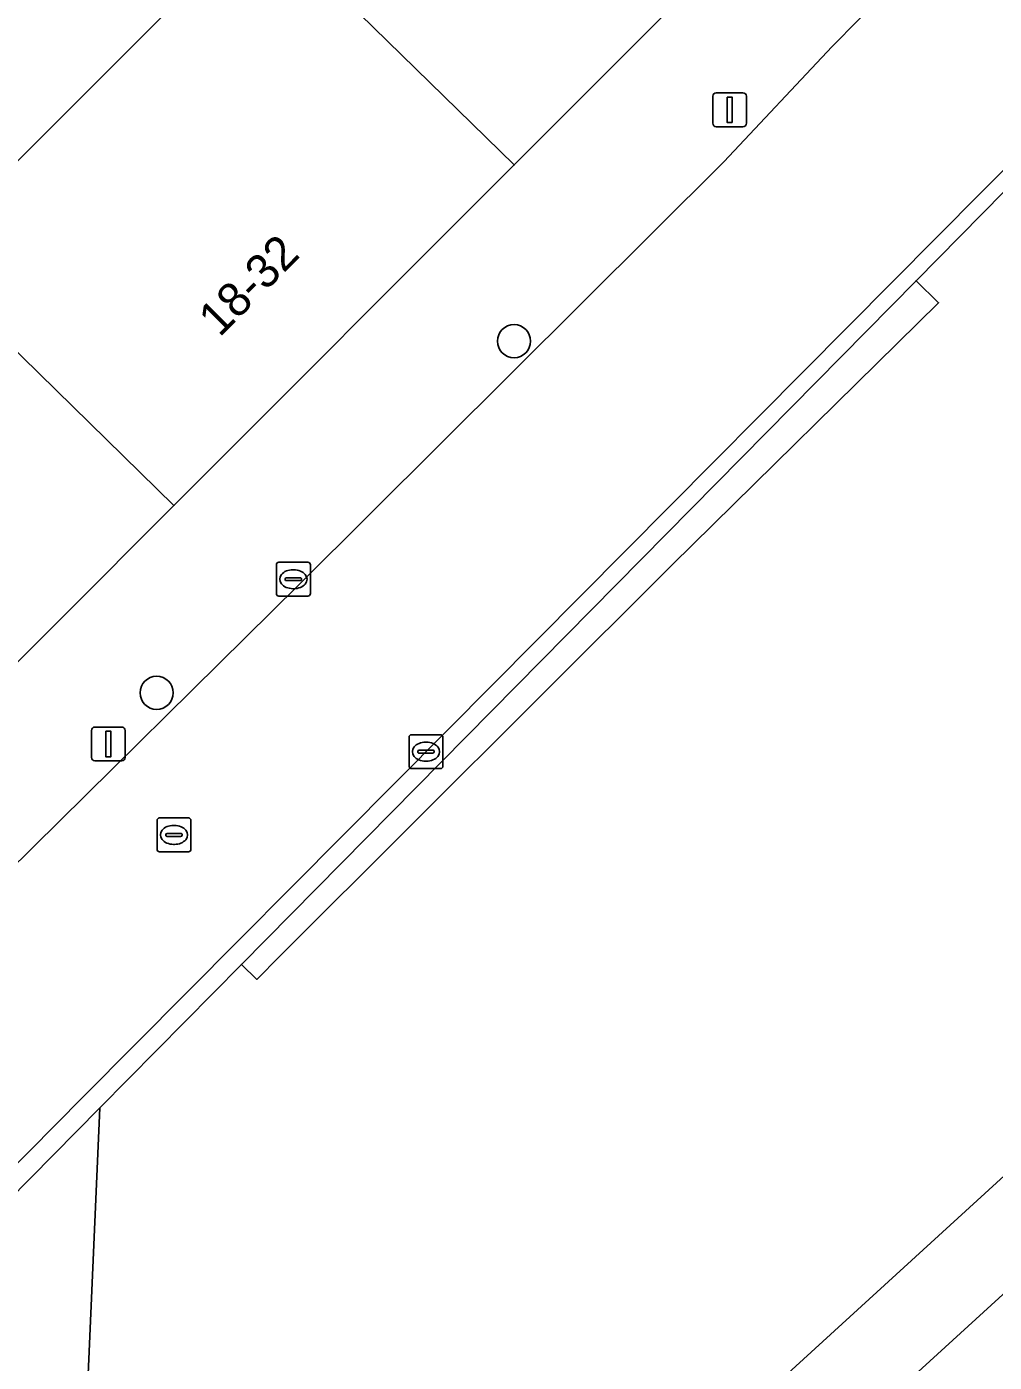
# Model space of a CAD drawing. Extents: x 159888 to 160761, y 384031 to 384750.
# Drawn here: x 160388.95 to 160417.48, y 384258.44 to 384297.83 of the extents above; entities that cross this region are included whole.
import ezdxf

# ---------------------------------------------------------------- set-up
doc = ezdxf.new("R2010")
doc.units = 0
for name, color, linetype in [('IMGEO_Boom', 7, 'Continuous'), ('IMGEO_Erf', 7, 'Continuous'), ('IMGEO_Groenvoorziening', 7, 'Continuous'), ('IMGEO_Kolk', 7, 'Continuous'), ('IMGEO_Lichtmast', 7, 'Continuous'), ('IMGEO_Pand', 7, 'Continuous'), ('IMGEO_Pand_nummerreeks', 7, 'Continuous'), ('IMGEO_Rijbaan_lokaal_open', 7, 'Continuous'), ('IMGEO_Rioolput', 7, 'Continuous'), ('IMGEO_Voetpad_halfverhard', 7, 'Continuous'), ('IMGEO_Voetpad_open', 7, 'Continuous')]:
    doc.layers.add(name, color=color, linetype=linetype)

msp = doc.modelspace()

# ---------------------------------------------------------------- linework, layer by layer
at = {"layer": 'IMGEO_Boom'}
for centre in [(160403.319, 384288.557), (160392.78, 384278.186)]:
    msp.add_circle(centre, 0.489, dxfattribs=at)
at = {"layer": 'IMGEO_Erf'}
for points in [[(160407.134, 384312.362), (160404.095, 384316.885), (160401.57, 384314.532), (160372.039, 384285.135), (160362.772, 384285.007), (160362.837, 384279.095), (160351.699, 384267.85), (160345.439, 384274.748), (160345.355, 384284.72), (160341.199, 384284.583), (160337.275, 384280.219), (160336.483, 384279.562), (160360.504, 384250.764), (160363.191, 384253.558), (160355.746, 384260.844), (160365.773, 384270.9), (160375.799, 384280.956), (160385.826, 384291.012), (160395.852, 384301.068), (160405.753, 384310.998)], [(160415.894, 384247.195), (160418.994, 384250), (160426.423, 384256.722), (160436.74, 384266.058), (160437.684, 384267.073), (160432.866, 384274.257), (160406.309, 384250), (160394.332, 384239.06), (160393.278, 384238.132), (160385.071, 384230.903), (160377.553, 384231.423), (160373.824, 384235.664), (160374.226, 384244.326), (160369.777, 384244.623), (160364.144, 384239.222), (160389.244, 384208.933), (160391.374, 384210.83), (160384.306, 384218.612), (160394.835, 384228.14), (160405.365, 384237.667)]]:
    msp.add_lwpolyline(points, close=True, dxfattribs=at)
at = {"layer": 'IMGEO_Groenvoorziening'}
msp.add_lwpolyline([(160418.424, 384293.635), (160415.176, 384290.342), (160415.838, 384289.689), (160407.979, 384281.961), (160396.416, 384270.415), (160395.73, 384269.729), (160395.281, 384270.172), (160391.104, 384265.938), (160390.406, 384250), (160390.241, 384246.234), (160394.04, 384242.242), (160402.528, 384250), (160431.422, 384276.411)], dxfattribs=at)
at = {"layer": 'IMGEO_Kolk'}
for p, q in [((160396.312, 384281.11), (160396.312, 384281.962)), ((160396.387, 384282.036), (160397.239, 384282.036)), ((160397.313, 384281.962), (160397.313, 384281.11)), ((160396.571, 384281.53), (160396.571, 384281.542)), ((160396.614, 384281.579), (160397.012, 384281.579)), ((160396.8, 384281.816), (160396.825, 384281.816)), ((160397.055, 384281.542), (160397.055, 384281.53)), ((160397.009, 384281.493), (160396.611, 384281.493)), ((160396.823, 384281.256), (160396.798, 384281.256)), ((160397.239, 384281.036), (160396.387, 384281.036)), ((160400.222, 384276.022), (160400.222, 384276.874)), ((160400.297, 384276.948), (160401.149, 384276.948)), ((160401.223, 384276.874), (160401.223, 384276.022)), ((160400.481, 384276.442), (160400.481, 384276.454)), ((160400.919, 384276.405), (160400.521, 384276.405)), ((160400.524, 384276.491), (160400.922, 384276.491)), ((160400.71, 384276.728), (160400.735, 384276.728)), ((160400.965, 384276.454), (160400.965, 384276.442)), ((160400.733, 384276.168), (160400.708, 384276.168)), ((160401.149, 384275.948), (160400.297, 384275.948))]:
    msp.add_line(p, q, dxfattribs=at)
for points in [[(160396.312, 384281.11), (160396.312, 384281.962)], [(160396.387, 384282.036), (160397.239, 384282.036)], [(160397.313, 384281.962), (160397.313, 384281.11)], [(160397.239, 384281.036), (160396.387, 384281.036)], [(160400.222, 384276.022), (160400.222, 384276.874)], [(160400.297, 384276.948), (160401.149, 384276.948)], [(160401.223, 384276.874), (160401.223, 384276.022)], [(160401.149, 384275.948), (160400.297, 384275.948)]]:
    msp.add_lwpolyline(points, dxfattribs=at)
for centre, radius, start, end in [((160396.389, 384281.96), 0.0765, 91.552, 178.448), ((160396.389, 384281.96), 0.0765, 91.552, 178.448), ((160397.237, 384281.96), 0.0765, 1.552, 88.448), ((160397.237, 384281.96), 0.0765, 1.552, 88.448), ((160396.611, 384281.539), 0.0403, 85.8775, 175.7526), ((160396.608, 384281.529), 0.0366, 178.938, 274.7102), ((160397.012, 384281.536), 0.043, 264.8664, 352.4533), ((160397.016, 384281.541), 0.0386, 1.7309, 96.639), ((160396.389, 384281.112), 0.0765, 181.552, 268.448), ((160396.389, 384281.112), 0.0765, 181.552, 268.448), ((160397.237, 384281.112), 0.0765, 271.552, 358.448), ((160397.237, 384281.112), 0.0765, 271.552, 358.448), ((160400.299, 384276.872), 0.0765, 91.552, 178.448), ((160400.299, 384276.872), 0.0765, 91.552, 178.448), ((160401.147, 384276.872), 0.0765, 1.552, 88.448), ((160401.147, 384276.872), 0.0765, 1.552, 88.448), ((160400.521, 384276.451), 0.0403, 85.8775, 175.7526), ((160400.518, 384276.441), 0.0366, 178.938, 274.7102), ((160400.922, 384276.448), 0.043, 264.8664, 352.4533), ((160400.926, 384276.453), 0.0386, 1.7309, 96.639), ((160400.299, 384276.024), 0.0765, 181.552, 268.448), ((160400.299, 384276.024), 0.0765, 181.552, 268.448), ((160401.147, 384276.024), 0.0765, 271.552, 358.448), ((160401.147, 384276.024), 0.0765, 271.552, 358.448)]:
    msp.add_arc(centre, radius, start, end, dxfattribs=at)
for centre, major_axis, ratio, start_param, end_param in [((160396.799, 384281.536), (-0.387, 0.002), 0.722429, 4.712389, 7.853982), ((160396.824, 384281.536), (-0.39, 0.002), 0.717154, 1.570796, 4.712389), ((160400.709, 384276.448), (-0.387, 0.002), 0.722429, 4.712389, 7.853982), ((160400.734, 384276.448), (-0.39, 0.002), 0.717154, 1.570796, 4.712389)]:
    msp.add_ellipse(centre, major_axis=major_axis, ratio=ratio, start_param=start_param, end_param=end_param, dxfattribs=at)
at = {"layer": 'IMGEO_Lichtmast'}
for p, q in [((160409.179, 384294.985), (160409.179, 384295.785)), ((160409.179, 384295.785), (160409.179, 384294.985)), ((160409.279, 384295.885), (160410.069, 384295.885)), ((160410.069, 384295.885), (160409.279, 384295.885)), ((160410.169, 384295.785), (160410.169, 384294.985)), ((160410.169, 384294.985), (160410.169, 384295.785)), ((160410.069, 384294.885), (160409.279, 384294.885)), ((160409.279, 384294.885), (160410.069, 384294.885)), ((160390.96, 384277.175), (160391.75, 384277.175)), ((160391.75, 384277.175), (160390.96, 384277.175)), ((160390.86, 384276.275), (160390.86, 384277.075)), ((160390.86, 384277.075), (160390.86, 384276.275)), ((160391.85, 384277.075), (160391.85, 384276.275)), ((160391.85, 384276.275), (160391.85, 384277.075)), ((160391.75, 384276.175), (160390.96, 384276.175)), ((160390.96, 384276.175), (160391.75, 384276.175))]:
    msp.add_line(p, q, dxfattribs=at)
for points in [[(160409.599, 384295.76), (160409.749, 384295.76), (160409.749, 384295.01), (160409.599, 384295.01), (160409.599, 384295.76)], [(160391.28, 384277.05), (160391.43, 384277.05), (160391.43, 384276.3), (160391.28, 384276.3), (160391.28, 384277.05)]]:
    msp.add_lwpolyline(points, dxfattribs=at)
for centre, start, end in [((160409.279, 384295.785), 90, 180), ((160409.279, 384295.785), 90, 180), ((160410.069, 384295.785), 0, 90), ((160410.069, 384295.785), 360, 90), ((160409.279, 384294.985), 180, 270), ((160409.279, 384294.985), 180, 270), ((160410.069, 384294.985), 270, 0), ((160410.069, 384294.985), 270, 0), ((160390.96, 384277.075), 90, 180), ((160390.96, 384277.075), 90, 180), ((160391.75, 384277.075), 0, 90), ((160391.75, 384277.075), 360, 90), ((160390.96, 384276.275), 180, 270), ((160390.96, 384276.275), 180, 270), ((160391.75, 384276.275), 270, 0), ((160391.75, 384276.275), 270, 0)]:
    msp.add_arc(centre, 0.1, start, end, dxfattribs=at)
at = {"layer": 'IMGEO_Pand'}
for points in [[(160395.852, 384301.068), (160403.325, 384293.755), (160413.221, 384303.667), (160405.753, 384310.998)], [(160393.291, 384283.706), (160403.325, 384293.755), (160395.852, 384301.068), (160385.826, 384291.012)], [(160383.258, 384273.657), (160393.291, 384283.706), (160385.826, 384291.012), (160375.799, 384280.956)]]:
    msp.add_lwpolyline(points, close=True, dxfattribs=at)
at = {"layer": 'IMGEO_Rijbaan_lokaal_open'}
for points in [[(160422.932, 384294.34), (160417.91, 384301.776), (160415.801, 384300.405), (160412.696, 384297.247), (160409.504, 384293.847), (160396.973, 384281.372), (160379.726, 384264.338), (160372.559, 384257.094), (160366.063, 384250.659), (160365.342, 384250), (160363.109, 384247.959), (160360.237, 384245.231), (160359.808, 384244.824), (160358.837, 384243.977), (160356.862, 384242.381), (160355.12, 384241.215), (160350.961, 384238.084), (160345.716, 384234.364), (160345.542, 384234.231)], [(160344.158, 384231.267), (160343.475, 384230.828), (160346.326, 384226.816), (160346.553, 384226.989), (160354.699, 384232.863), (160360.784, 384237.351), (160361.189, 384237.649), (160363.689, 384239.781), (160364.647, 384240.62), (160366.673, 384242.576), (160373.037, 384248.641), (160374.399, 384250), (160384.224, 384259.805), (160390.609, 384266.27), (160401.354, 384277.085), (160418.41, 384294.276)]]:
    msp.add_lwpolyline(points, dxfattribs=at)
at = {"layer": 'IMGEO_Rioolput'}
for p, q in [((160392.791, 384273.567), (160392.791, 384274.419)), ((160392.866, 384274.493), (160393.718, 384274.493)), ((160393.792, 384274.419), (160393.792, 384273.567)), ((160393.093, 384274.036), (160393.491, 384274.036)), ((160393.279, 384274.273), (160393.304, 384274.273)), ((160393.05, 384273.987), (160393.05, 384273.999)), ((160393.488, 384273.95), (160393.09, 384273.95)), ((160393.302, 384273.713), (160393.277, 384273.713)), ((160393.534, 384273.999), (160393.534, 384273.987)), ((160393.718, 384273.493), (160392.866, 384273.493))]:
    msp.add_line(p, q, dxfattribs=at)
for points in [[(160392.791, 384273.567), (160392.791, 384274.419)], [(160392.866, 384274.493), (160393.718, 384274.493)], [(160393.792, 384274.419), (160393.792, 384273.567)], [(160393.718, 384273.493), (160392.866, 384273.493)]]:
    msp.add_lwpolyline(points, dxfattribs=at)
for centre, radius, start, end in [((160392.868, 384274.417), 0.0765, 91.552, 178.448), ((160392.868, 384274.417), 0.0765, 91.552, 178.448), ((160393.716, 384274.417), 0.0765, 1.552, 88.448), ((160393.716, 384274.417), 0.0765, 1.552, 88.448), ((160393.09, 384273.996), 0.0403, 85.8775, 175.7526), ((160393.495, 384273.998), 0.0386, 1.7309, 96.639), ((160393.087, 384273.986), 0.0366, 178.938, 274.7102), ((160393.491, 384273.993), 0.043, 264.8664, 352.4533), ((160392.868, 384273.569), 0.0765, 181.552, 268.448), ((160392.868, 384273.569), 0.0765, 181.552, 268.448), ((160393.716, 384273.569), 0.0765, 271.552, 358.448), ((160393.716, 384273.569), 0.0765, 271.552, 358.448)]:
    msp.add_arc(centre, radius, start, end, dxfattribs=at)
for centre, major_axis, ratio, start_param, end_param in [((160393.278, 384273.993), (-0.387, 0.002), 0.722429, 4.712389, 7.853982), ((160393.303, 384273.993), (-0.39, 0.002), 0.717154, 1.570796, 4.712389)]:
    msp.add_ellipse(centre, major_axis=major_axis, ratio=ratio, start_param=start_param, end_param=end_param, dxfattribs=at)
at = {"layer": 'IMGEO_Voetpad_halfverhard'}
msp.add_lwpolyline([(160390.241, 384246.234), (160390.406, 384250), (160391.104, 384265.938), (160388.378, 384263.174), (160387.768, 384250), (160387.57, 384245.716), (160371.882, 384246.688), (160369.777, 384244.623), (160374.226, 384244.326), (160388.452, 384243.469), (160393.278, 384238.132), (160394.332, 384239.06), (160406.309, 384250), (160432.866, 384274.257), (160431.422, 384276.411), (160402.528, 384250), (160394.04, 384242.242)], close=True, dxfattribs=at)
at = {"layer": 'IMGEO_Voetpad_open'}
for points in [[(160412.696, 384297.247), (160415.801, 384300.405), (160413.221, 384303.667), (160403.325, 384293.755), (160393.291, 384283.706), (160383.258, 384273.657), (160373.224, 384263.607), (160363.191, 384253.558), (160360.504, 384250.764), (160358.209, 384248.5), (160357.767, 384248.02), (160354.731, 384245.687), (160340.225, 384235.253), (160343.475, 384230.828), (160344.158, 384231.267)], [(160345.542, 384234.231), (160345.716, 384234.364), (160350.961, 384238.084), (160355.12, 384241.215), (160356.862, 384242.381), (160358.837, 384243.977), (160359.808, 384244.824), (160360.237, 384245.231), (160359.618, 384245.884), (160362.49, 384248.612), (160363.109, 384247.959), (160365.342, 384250), (160366.063, 384250.659), (160372.559, 384257.094), (160379.726, 384264.338), (160396.973, 384281.372), (160409.504, 384293.847), (160412.696, 384297.247)], [(160418.41, 384294.276), (160401.354, 384277.085), (160390.609, 384266.27), (160384.224, 384259.805), (160374.399, 384250), (160373.037, 384248.641), (160366.673, 384242.576), (160364.647, 384240.62), (160363.689, 384239.781), (160361.189, 384237.649), (160360.784, 384237.351), (160354.699, 384232.863), (160346.553, 384226.989), (160346.326, 384226.816), (160346.64, 384226.054), (160361.616, 384237.146), (160364.144, 384239.222), (160369.777, 384244.623), (160371.882, 384246.688), (160375.258, 384250), (160388.378, 384263.174), (160391.104, 384265.938), (160395.281, 384270.172), (160415.176, 384290.342)], [(160415.176, 384290.342), (160418.424, 384293.635)]]:
    msp.add_lwpolyline(points, dxfattribs=at)
msp.add_lwpolyline([(160407.979, 384281.961), (160415.838, 384289.689), (160415.176, 384290.342), (160395.281, 384270.172), (160395.73, 384269.729), (160396.416, 384270.415)], close=True, dxfattribs=at)

# ---------------------------------------------------------------- texts
at = {"layer": 'IMGEO_Pand_nummerreeks'}
msp.add_text('18-32', height=1, rotation=45.1059, dxfattribs=at).set_placement((160394.633, 384288.652))

doc.saveas('drawing.dxf')
